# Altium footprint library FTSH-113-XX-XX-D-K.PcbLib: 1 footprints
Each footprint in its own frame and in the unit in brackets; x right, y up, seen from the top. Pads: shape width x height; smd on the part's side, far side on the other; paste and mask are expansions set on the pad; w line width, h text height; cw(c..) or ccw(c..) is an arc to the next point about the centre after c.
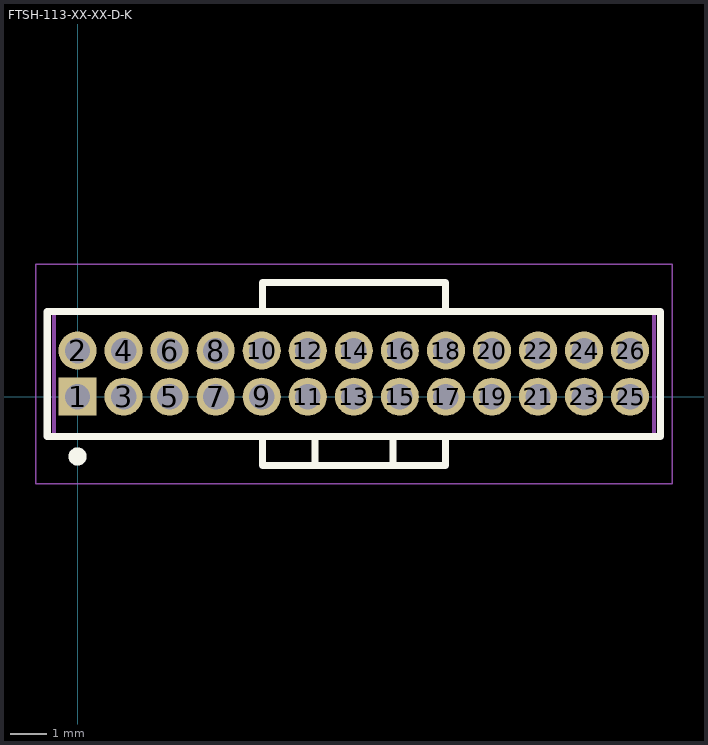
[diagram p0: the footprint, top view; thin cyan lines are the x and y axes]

## FTSH-113-XX-XX-D-K [mm] "1.27mm pitch, 26 pin, terminal strip; double row, PTH"
height 3.05
pads (26):
  rect 1.05x1.05 / inner round 1.05 / far side rect 1.05x1.05 hole 0.7 mask+0: 1(0,0)
  round 1.05 hole 0.7 mask+0: 2(0,1.27) 3(1.27,0) 4(1.27,1.27) 5(2.54,0) 6(2.54,1.27) 7(3.81,0) 8(3.81,1.27) 9(5.08,0) 10(5.08,1.27) 11(6.35,0) 12(6.35,1.27) 13(7.62,0) 14(7.62,1.27) 15(8.89,0) 16(8.89,1.27) 17(10.16,0) 18(10.16,1.27) 19(11.43,0) 20(11.43,1.27) 21(12.7,0) 22(12.7,1.27) 23(13.97,0) 24(13.97,1.27) 25(15.24,0) 26(15.24,1.27)
Top Overlay:
  circle w0.25: c0,-1.65 r0.125
  lines w0.2: 5.1,-1.1 5.1,-1.9 10.15,-1.9 10.15,-1.1 ; 5.1,2.35 5.1,3.15 10.15,3.15 10.15,2.35 ; 6.55,-1.9 6.55,-1.1 ; 8.7,-1.9 8.7,-1.1 ; -0.838,-1.1 -0.838,2.35 16.078,2.35 16.078,-1.1 -0.838,-1.1
Mechanical 12:
  lines w0.001: -0.65,-1.1 -0.65,2.35 5.1,2.35 5.1,3.15 10.15,3.15 10.15,2.35 15.9,2.35 15.9,-1.1 10.15,-1.1 10.15,-1.9 5.1,-1.9 5.1,-1.1 -0.65,-1.1
Mechanical 13:
  lines w0.1: 5.1,-1.1 5.1,-1.9 10.15,-1.9 10.15,-1.1 ; 5.1,2.35 5.1,3.15 10.15,3.15 10.15,2.35 ; 6.55,-1.9 6.55,-1.1 ; 8.7,-1.9 8.7,-1.1 ; -0.65,-1.1 -0.65,2.35 15.9,2.35 15.9,-1.1 -0.65,-1.1
  text ".Designator" at 0,0 h1.52
Mechanical 15:
  lines w0.05: -1.15,-2.4 -1.15,3.65 16.4,3.65 16.4,-2.4 -1.15,-2.4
